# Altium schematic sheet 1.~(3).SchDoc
size 420 x 297 mm
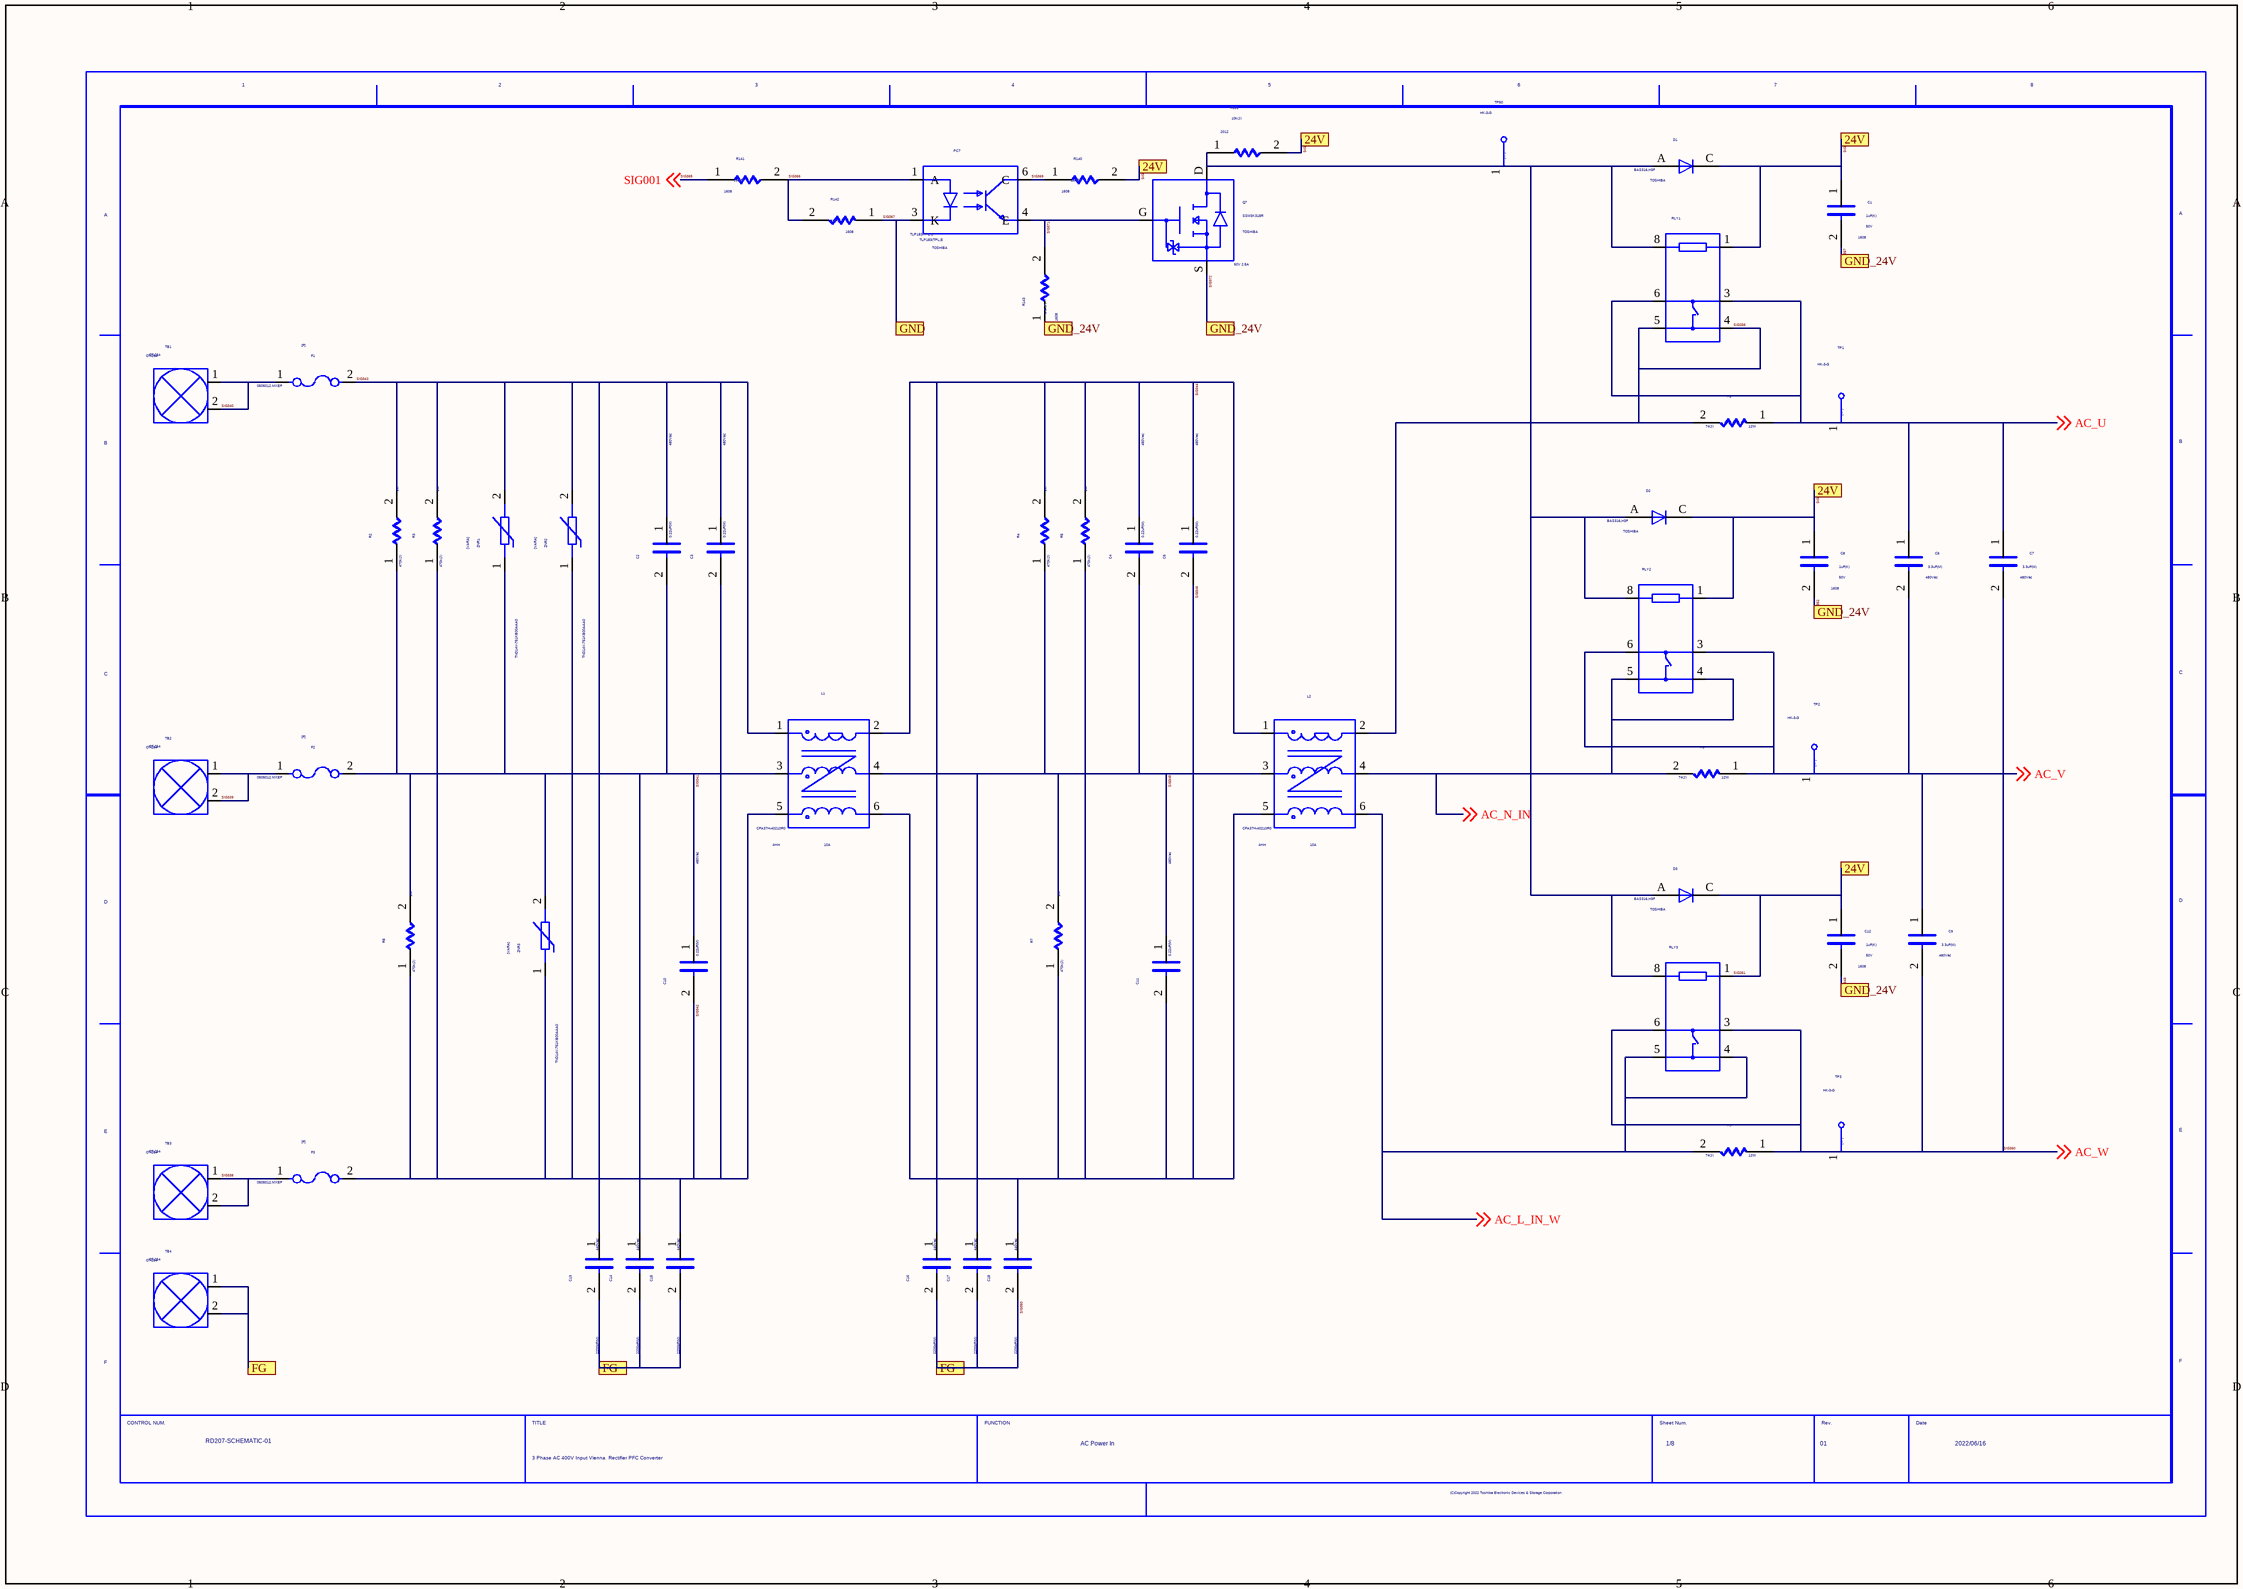
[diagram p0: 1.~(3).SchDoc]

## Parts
C1  SIZECODESMD: 1608  VAL2: 50V  VAL1: 1uF(K)  (hidden comment: C)
C2  VAL2: 480Vac  VAL1: 0.22uF(M)  (hidden comment: C)
C3  VAL2: 480Vac  VAL1: 0.22uF(M)  (hidden comment: C)
C4  VAL2: 480Vac  VAL1: 0.22uF(M)  (hidden comment: C)
C5  VAL2: 480Vac  VAL1: 0.22uF(M)  (hidden comment: C)
C6  VAL2: 480Vac  VAL1: 3.3uF(M)  (hidden comment: C)
C7  VAL2: 480Vac  VAL1: 3.3uF(M)  (hidden comment: C)
C8  SIZECODESMD: 1608  VAL2: 50V  VAL1: 1uF(K)  (hidden comment: C)
C9  VAL2: 480Vac  VAL1: 3.3uF(M)  (hidden comment: C)
C10  VAL2: 480Vac  VAL1: 0.22uF(M)  (hidden comment: C)
C11  VAL2: 480Vac  VAL1: 0.22uF(M)  (hidden comment: C)
C12  SIZECODESMD: 1608  VAL2: 50V  VAL1: 1uF(K)  (hidden comment: C)
C13  VAL2: 440Vac  VAL1: 2200pF(M)  (hidden comment: C)
C14  VAL2: 440Vac  VAL1: 2200pF(M)  (hidden comment: C)
C15  VAL2: 440Vac  VAL1: 2200pF(M)  (hidden comment: C)
C16  VAL2: 440Vac  VAL1: 2200pF(M)  (hidden comment: C)
C17  VAL2: 440Vac  VAL1: 2200pF(M)  (hidden comment: C)
C18  VAL2: 440Vac  VAL1: 2200pF(M)  (hidden comment: C)
D1  USERCOMPTEXT3: TOSHIBA  VAL3: BAS316,H3F  (hidden comment: D)
D2  USERCOMPTEXT3: TOSHIBA  VAL3: BAS316,H3F  (hidden comment: D)
D3  USERCOMPTEXT3: TOSHIBA  VAL3: BAS316,H3F  (hidden comment: D)
F1  VAL3: 0505012.MXEP  (hidden comment: F)
F2  VAL3: 0505012.MXEP  (hidden comment: F)
F3  VAL3: 0505012.MXEP  (hidden comment: F)
L1  VAL2: 10A  VAL1: 4mH  (hidden comment: CFA37H-40210R0)
L2  VAL2: 10A  VAL1: 4mH  (hidden comment: CFA37H-40210R0)
PC7  TLP183(TPL,E  USERCOMPTEXT3: TOSHIBA
Q7  NOTE: 60V 2.5A  USERCOMPTEXT3: TOSHIBA  (hidden comment: SSM3K318R)
R1  VAL2: 12W  VAL1: 74(J)  (hidden comment: R)
R2  VAL2: 1W  VAL1: 470k(J)  (hidden comment: R)
R3  VAL2: 1W  VAL1: 470k(J)  (hidden comment: R)
R4  VAL2: 1W  VAL1: 470k(J)  (hidden comment: R)
R5  VAL2: 1W  VAL1: 470k(J)  (hidden comment: R)
R6  VAL2: 12W  VAL1: 74(J)  (hidden comment: R)
R7  VAL2: 1W  VAL1: 470k(J)  (hidden comment: R)
R8  VAL2: 1W  VAL1: 470k(J)  (hidden comment: R)
R9  VAL2: 12W  VAL1: 74(J)  (hidden comment: R)
R139  SIZECODESMD: 2012  VAL1: 10k(J)  (hidden comment: R)
R140  SIZECODESMD: 1608  VAL1: 10k(F)  (hidden comment: R)
R141  SIZECODESMD: 1608  VAL1: 390(F)  (hidden comment: R)
R142  SIZECODESMD: 1608  VAL1: 1k(F)  (hidden comment: R)
R143  SIZECODESMD: 1608  VAL1: 3.9k(F)  (hidden comment: R)
RLY1  G2RL-1A4-E-CF DC24  (value not drawn)
RLY2  G2RL-1A4-E-CF DC24  (value not drawn)
RLY3  G2RL-1A4-E-CF DC24  (value not drawn)
TB1  OT-264
TB2  OT-264
TB3  OT-264
TB4  OT-264
TP1  VAL3: HK-3-G  (hidden comment: TP)
TP2  VAL3: HK-3-G  (hidden comment: TP)
TP3  VAL3: HK-3-G  (hidden comment: TP)
TP50  VAL3: HK-3-G  (hidden comment: TP)
U?  DATE: 2022/06/16  TITLE: 3 Phase AC 400V Input Vienna / Rectifier PFC Converter  REVISION: 01  SHEETNUMBER: 1/8  FUNCTION: AC Power In  DRAWINGNUMBER: RD207-SCHEMATIC-01  (hidden comment: WAKU_DEF100)
ZNR1  VAL3: TND14V-751KB00AAA0  (hidden comment: VARA)
ZNR2  VAL3: TND14V-751KB00AAA0  (hidden comment: VARA)
ZNR3  VAL3: TND14V-751KB00AAA0  (hidden comment: VARA)

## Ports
24V, FG, GND, GND_24V

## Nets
/MainRLY_24V: D1.A D2.A D3.A Q7.D R139.1 RLY1.8 RLY2.8 RLY3.8 TP50.1
AC_L_IN_W: L2.6 R9.2 RLY3.4 RLY3.5 ; off-sheet AC_L_IN_W
AC_N_IN: L2.4 R6.2 RLY2.4 RLY2.5 ; off-sheet AC_N_IN
AC_U: C6.1 C7.1 R1.1 RLY1.3 RLY1.6 TP1.1 ; off-sheet AC_U
AC_V: C6.2 C9.1 R6.1 RLY2.3 RLY2.6 TP2.1 ; off-sheet AC_V
SIG338: F3.1 TB3.1 TB3.2
SIG339: F2.1 TB2.1 TB2.2
SIG340: F1.1 TB1.1 TB1.2
SIG341: C2.2 C10.1 C14.1 F2.2 L1.3 R2.1 R8.2 ZNR1.1 ZNR3.2
SIG342: C3.2 C10.2 C15.1 F3.2 L1.5 R3.1 R8.1 ZNR2.1 ZNR3.1
SIG343: C2.1 C3.1 C13.1 F1.2 L1.1 R2.2 R3.2 ZNR1.2 ZNR2.2
SIG344: C4.1 C5.1 C16.1 L1.2 L2.1 R4.2 R5.2
SIG345: C4.2 C11.1 C17.1 L1.4 L2.3 R4.1 R7.2
SIG346: C5.2 C11.2 C18.1 L1.6 L2.5 R5.1 R7.1
SIG348: C1.2 C8.2 C12.2 Q7.S R143.1 ; port GND_24V  [also labelled SIG352, SIG357, SIG372]
SIG350: C13.2 C14.2 C15.2 C16.2 C17.2 C18.2 TB4.1 TB4.2 ; port FG
SIG351: C1.1 C8.1 C12.1 D1.C D2.C D3.C R139.2 R140.2 RLY1.1 RLY2.1 RLY3.1 ; port 24V  [also labelled SIG353, SIG358, SIG370, SIG373]
SIG356: L2.2 R1.2 RLY1.4 RLY1.5
SIG360: C7.2 C9.2 R9.1 RLY3.3 RLY3.6 TP3.1 ; off-sheet AC_W  [also labelled AC_W]
SIG365: R141.1 ; off-sheet SIG001  [also labelled SIG001]
SIG366: PC7.1(A) R141.2 R142.2
SIG367: PC7.3(K) R142.1 ; port GND
SIG369: PC7.6(C) R140.1
SIG371: PC7.4(E) Q7.G R143.2

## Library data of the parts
C1 C8 C12 = C: OriginalSymbolOrigin: (2540,7620); COMP: -C-UMK107AB7105KA-T
C2-C5 C10 C11 = C: OriginalSymbolOrigin: (2540,7620); COMP: -C-F339X142248MIP2T0
C6 C7 C9 = C: OriginalSymbolOrigin: (2540,7620); COMP: -C-F340X153348MPP2T0
C13-C18 = C: OriginalSymbolOrigin: (2540,7620); COMP: -C-CD45-E2GA222M-VKA
D1-D3 = D: SAVEAREA0: -225,-91,12804,7836; SAVECOUNT: 3; TIME: 14:49:55; UPDATEUSER: 19870035; UPDATETIME: 14:20:16; OriginalSymbolOrigin: (5080,5080); COMP: -D-BAS316_H3F_AC
F1-F3 = F: OriginalSymbolOrigin: (2540,5080); COMP: F-0505012.MXEP
L1 L2 = CFA37H_40210R0: 3phase Common Mode Choke; COMP: L-CFA37H-40210R0; MAKER: Tamura; NOTE: 3phase, 4mH@100kHz, 10A; TIME: 11:39:42; UPDATEUSER: t5459927; UPDATETIME: 15:32:41; SAVECOUNT: 2; SAVEAREA0: -28588,-28970,43380,3822; OriginalSymbolOrigin: (0,0)
PC7 = TLP183: Photocoupler; COMP: -PC-TLP183_TPL_E; TIME: 11:39:41; UPDATEUSER: t5459927; UPDATETIME: 14:44:44; SAVECOUNT: 2; SAVEAREA0: -18362,-25993,35930,13752; OriginalSymbolOrigin: (0,0)
Q7 = SSM3K318R: MOSFET; COMP: -Q-SSM3K318R; TIME: 11:39:41; UPDATEUSER: t5459927; SAVECOUNT: 1; SAVEAREA0: -8920,-18190,20944,3672; OriginalSymbolOrigin: (0,0); INSTANCENAME: INS17447591
R1 R6 R9 = R: OriginalSymbolOrigin: (5080,5080); COMP: R-MNG12E740JC
R2-R5 R7 R8 = R: OriginalSymbolOrigin: (5080,5080); COMP: -R-RCR60C474J
R139 = R: OriginalSymbolOrigin: (5080,5080); VAL2: 250mW; COMP: -R-RK73B2ATTD103J
R140 = R: OriginalSymbolOrigin: (5080,5080); VAL2: 100mW; COMP: -R-ERJ3EKF1002V
R141 = R: OriginalSymbolOrigin: (5080,5080); VAL2: 100mW; COMP: -R-ERJ3EKF3900V
R142 = R: OriginalSymbolOrigin: (5080,5080); VAL2: 125mW; COMP: -R-RK73H1JTTD1001F
R143 = R: OriginalSymbolOrigin: (5080,5080); VAL2: 100mW; COMP: -R-ERJ3EKF3901V
RLY1-RLY3 = G2RL_1A4_E_CF_DC24: Power Relay; MANUFACTURER: OMRON; COMP: -RLY-G2RL-1A4-E-CF_DC24; NOTE: 16A AC250V; TIME: 11:39:42; UPDATEUSER: t5459927; UPDATETIME: 16:09:17; SAVECOUNT: 4; SAVEAREA0: -30398,-23390,50563,13500; OriginalSymbolOrigin: (5080,7620)
TB1-TB4 = OT_264: Terminal, 50A, M4; MANUFACTURER: Osada; COMP: -TB-OT-264; TIME: 11:39:39; UPDATEUSER: t5459927; SAVECOUNT: 1; SAVEAREA0: -3825,-10384,11105,546; OriginalSymbolOrigin: (0,0); REFERENCE TEMPLATE: TB; INSTANCENAME: INS1928
TP1-TP3 TP50 = TP: TIME: 16:12:21; UPDATEUSER: fukuda-y; UPDATETIME: 16:18:11; SAVECOUNT: 2; SAVEAREA0: -242,-92,12810,7836; OriginalSymbolOrigin: (0,7620); COMP: -TP-HK-3-G
U? = WAKU_DEF100: PLOTTIME: HH:MM; SAVEAREA0: 22200,72372,612276,319236; TIME: 14:30:25; UPDATEUSER: t5459927; UPDATETIME: 09:21:32; SAVECOUNT: 7; OriginalSymbolOrigin: (10160,284480)
ZNR1-ZNR3 = VARA: SAVEAREA0: -9950,-8554,25168,13619; SAVECOUNT: 12; TIME: 09:56:50; UPDATEUSER: tomizawa-y; OriginalSymbolOrigin: (2540,5080); COMP: -ZNR-TND14V-751KB00AAA0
